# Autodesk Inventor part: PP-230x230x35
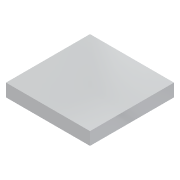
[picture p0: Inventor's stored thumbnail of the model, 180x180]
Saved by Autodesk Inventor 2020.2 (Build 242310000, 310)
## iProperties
Created: 2015-11
Part Number: PP-230x230x35
Material: Ogólny
Document SubType Name: Modeling
Designer: F.Stasiak
Density: 1 g/cm^3
Appearance: Przezroczyste
Catalog Web Link: www.expertbooks.pl
Manager: www.cadconsulting.pl
Company: Fabian Stasiak CAD Consulting
Author: F.Stasiak
Subject: Zbiór ćwiczeń. Autodesk Inventor 2020. Kurs Professional
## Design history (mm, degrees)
sketch "Szkic1"
  geometry: L1 (-115, 115)-(115, 115); L2 (115, 115)-(115, -115); L3 (115, -115)-(-115, -115); L4 (-115, -115)-(-115, 115); L5 (-115, 115)-(115, -115); L6 (115, 115)-(-115, -115); 1 further point
  constraints: 12 end point, 2 midpoint, 2 parallel, 1 horizontal, 1 perpendicular
  dimensions: "d0" = 230 distance of L2.end L3.end; "d1" = 230 distance of L1.end L2.end
extrude "Wyciągnięcie proste1" new body sketch "Szkic1" distance "d2" = 35; taper "d3" = 0 deg
node "Bryła1"
